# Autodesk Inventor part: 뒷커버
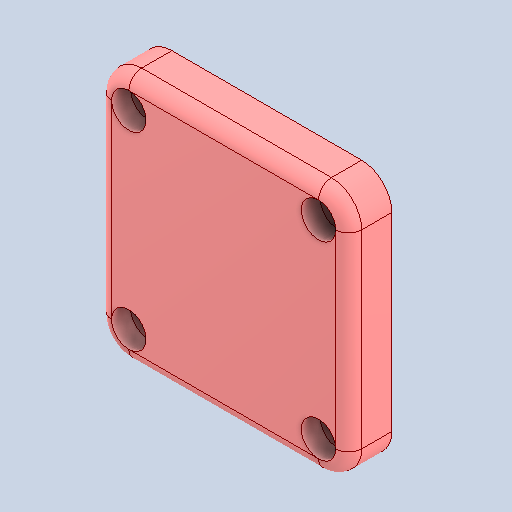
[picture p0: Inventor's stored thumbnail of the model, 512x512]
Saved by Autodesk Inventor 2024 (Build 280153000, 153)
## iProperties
Created: 2026-01
Part Number: 뒷커버
Material: 알루미늄 6061
Document SubType Name: Modeling
Designer: 2-10
Density: 2.7 g/cm^3
Appearance: 기본값
Author: jhkim
Sending System: Autodesk Inventor 2026
Preprocessor: ST-DEVELOPER v20.1
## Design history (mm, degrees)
node "뒷커버1"
node "솔리드2"
node "솔리드1"
